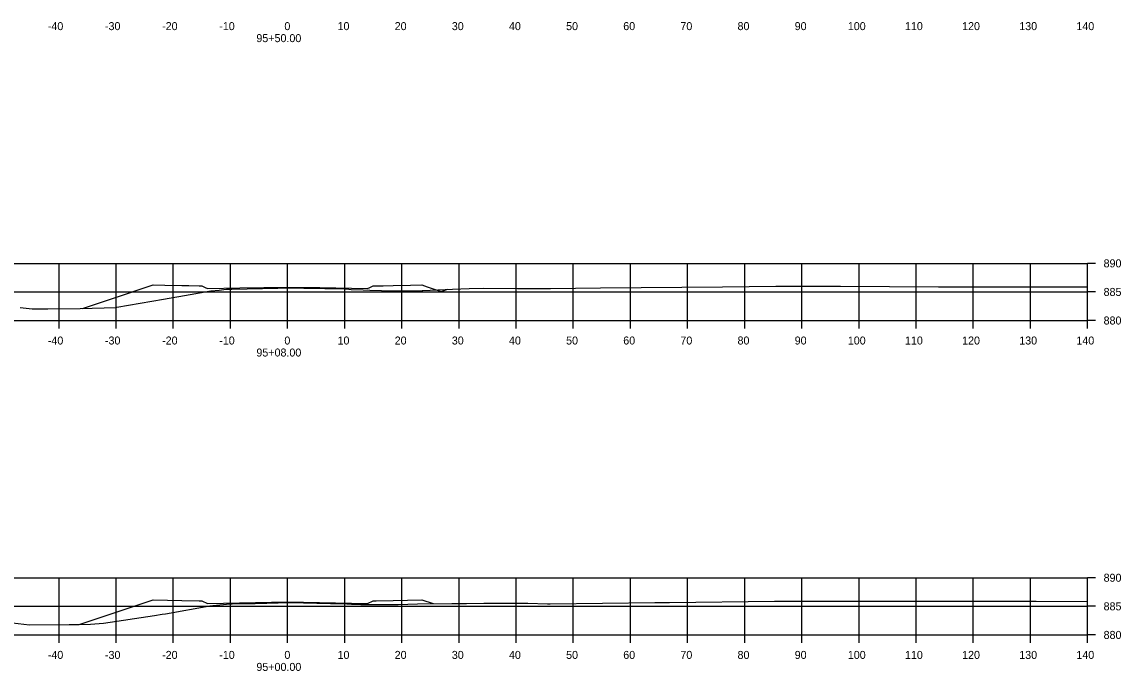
# Model space of a CAD drawing. Extents: x 1098669 to 1198896, y 698679 to 704410.
# Drawn here: x 1113452.4 to 1113644.7, y 701452.2 to 701565.8 of the extents above; entities that cross this region are included whole.
import ezdxf

# ---------------------------------------------------------------- set-up
doc = ezdxf.new("R2010")
doc.units = 0
for name, color, linetype in [('R_Alt Surface', 7, 'Continuous'), ('R_Axis', 7, 'Continuous'), ('R_Axis Annot', 7, 'Continuous'), ('R_Fin Surface', 7, 'Continuous'), ('R_Grid', 7, 'Continuous')]:
    doc.layers.add(name, color=color, linetype=linetype)

msp = doc.modelspace()

# ---------------------------------------------------------------- linework, layer by layer
at = {"layer": 'R_Alt Surface'}
for points in [[(1113452.08, 701515.81), (1113454.15, 701515.58), (1113456.94, 701515.59), (1113462.56, 701515.64), (1113468.89, 701515.86), (1113468.91, 701515.86), (1113469, 701515.87), (1113477.18, 701517.3), (1113480.82, 701517.94), (1113485.43, 701518.75), (1113486.92, 701518.89), (1113487.73, 701518.99), (1113488.18, 701519.02), (1113489.14, 701519.07), (1113497.15, 701519.23), (1113499.26, 701519.27), (1113501.73, 701519.23), (1113509.02, 701519.1), (1113509.58, 701519.05), (1113509.98, 701519.01), (1113512.08, 701518.95), (1113513.26, 701518.89), (1113517.34, 701518.77), (1113521.94, 701518.78), (1113522.43, 701518.79), (1113522.55, 701518.79), (1113527.72, 701519.07), (1113530.64, 701519.16), (1113533.08, 701519.21), (1113539.08, 701519.18), (1113540.74, 701519.17), (1113541.14, 701519.18), (1113544.85, 701519.15), (1113553.63, 701519.25), (1113574.97, 701519.44), (1113584.34, 701519.54), (1113595.62, 701519.54), (1113612.78, 701519.46), (1113618.71, 701519.47), (1113629.6, 701519.47), (1113638.87, 701519.44)], [(1113450.73, 701460.67), (1113453.7, 701460.34), (1113460.64, 701460.36), (1113462.39, 701460.38), (1113464.39, 701460.45), (1113466.65, 701460.6), (1113475.59, 701461.93), (1113476.91, 701462.16), (1113477.5, 701462.27), (1113485.26, 701463.63), (1113485.76, 701463.68), (1113487.65, 701463.89), (1113488.7, 701463.97), (1113489.18, 701464), (1113493.17, 701464.08), (1113499.28, 701464.2), (1113506.38, 701464.08), (1113509.04, 701464.03), (1113509.25, 701464.02), (1113510.03, 701463.94), (1113511.69, 701463.89), (1113514.28, 701463.9), (1113518.2, 701463.87), (1113521.61, 701464), (1113527.59, 701464.07), (1113530.19, 701464.08), (1113533.19, 701464.14), (1113536.63, 701464.13), (1113540.91, 701464.13), (1113544.37, 701464.02), (1113544.8, 701464.02), (1113563.14, 701464.22), (1113565.69, 701464.24), (1113584.08, 701464.44), (1113605.72, 701464.45), (1113607.62, 701464.44), (1113608.29, 701464.44), (1113629.88, 701464.45), (1113638.87, 701464.42)]]:
    msp.add_lwpolyline(points, dxfattribs=at)
at = {"layer": 'R_Axis'}
for p, q in [((1113638.87, 701513.56), (1113638.87, 701523.56)), ((1113640.27, 701523.56), (1113638.87, 701523.56)), ((1113640.27, 701518.56), (1113638.87, 701518.56)), ((1113358.87, 701513.56), (1113638.87, 701513.56)), ((1113458.87, 701512.16), (1113458.87, 701513.56)), ((1113468.87, 701512.16), (1113468.87, 701513.56)), ((1113478.87, 701512.16), (1113478.87, 701513.56)), ((1113488.87, 701512.16), (1113488.87, 701513.56)), ((1113498.87, 701512.16), (1113498.87, 701513.56)), ((1113508.87, 701512.16), (1113508.87, 701513.56)), ((1113518.87, 701512.16), (1113518.87, 701513.56)), ((1113528.87, 701512.16), (1113528.87, 701513.56)), ((1113538.87, 701512.16), (1113538.87, 701513.56)), ((1113548.87, 701512.16), (1113548.87, 701513.56)), ((1113558.87, 701512.16), (1113558.87, 701513.56)), ((1113568.87, 701512.16), (1113568.87, 701513.56)), ((1113578.87, 701512.16), (1113578.87, 701513.56)), ((1113588.87, 701512.16), (1113588.87, 701513.56)), ((1113598.87, 701512.16), (1113598.87, 701513.56)), ((1113608.87, 701512.16), (1113608.87, 701513.56)), ((1113618.87, 701512.16), (1113618.87, 701513.56)), ((1113628.87, 701512.16), (1113628.87, 701513.56)), ((1113638.87, 701512.16), (1113638.87, 701513.56)), ((1113640.27, 701513.56), (1113638.87, 701513.56)), ((1113638.87, 701458.56), (1113638.87, 701468.56)), ((1113640.27, 701468.56), (1113638.87, 701468.56)), ((1113640.27, 701463.56), (1113638.87, 701463.56)), ((1113358.87, 701458.56), (1113638.87, 701458.56)), ((1113458.87, 701457.16), (1113458.87, 701458.56)), ((1113468.87, 701457.16), (1113468.87, 701458.56)), ((1113478.87, 701457.16), (1113478.87, 701458.56)), ((1113488.87, 701457.16), (1113488.87, 701458.56)), ((1113498.87, 701457.16), (1113498.87, 701458.56)), ((1113508.87, 701457.16), (1113508.87, 701458.56)), ((1113518.87, 701457.16), (1113518.87, 701458.56)), ((1113528.87, 701457.16), (1113528.87, 701458.56)), ((1113538.87, 701457.16), (1113538.87, 701458.56)), ((1113548.87, 701457.16), (1113548.87, 701458.56)), ((1113558.87, 701457.16), (1113558.87, 701458.56)), ((1113568.87, 701457.16), (1113568.87, 701458.56)), ((1113578.87, 701457.16), (1113578.87, 701458.56)), ((1113588.87, 701457.16), (1113588.87, 701458.56)), ((1113598.87, 701457.16), (1113598.87, 701458.56)), ((1113608.87, 701457.16), (1113608.87, 701458.56)), ((1113618.87, 701457.16), (1113618.87, 701458.56)), ((1113628.87, 701457.16), (1113628.87, 701458.56)), ((1113638.87, 701457.16), (1113638.87, 701458.56)), ((1113640.27, 701458.56), (1113638.87, 701458.56))]:
    msp.add_line(p, q, dxfattribs=at)
at = {"layer": 'R_Fin Surface'}
for points in [[(1113462.98, 701515.65), (1113468.05, 701517.34), (1113475.37, 701519.78), (1113477.38, 701519.74), (1113480.37, 701519.68), (1113481.57, 701519.66), (1113483.37, 701519.62), (1113483.57, 701519.62), (1113483.87, 701519.62), (1113484.47, 701519.34), (1113484.87, 701519.14), (1113490.52, 701519.26), (1113498.87, 701519.42), (1113504.52, 701519.31), (1113512.87, 701519.14), (1113513.27, 701519.34), (1113513.87, 701519.62), (1113514.07, 701519.62), (1113514.37, 701519.62), (1113515.57, 701519.65), (1113517.37, 701519.68), (1113520.38, 701519.74), (1113522.37, 701519.78), (1113523.32, 701519.47), (1113525.76, 701518.65), (1113526.91, 701519.04)], [(1113462.42, 701460.38), (1113475.37, 701464.69), (1113480.37, 701464.59), (1113483.37, 701464.53), (1113483.87, 701464.53), (1113484.87, 701464.05), (1113498.87, 701464.33), (1113512.87, 701464.05), (1113513.87, 701464.53), (1113514.37, 701464.53), (1113517.37, 701464.59), (1113522.37, 701464.69), (1113524.34, 701464.03)]]:
    msp.add_lwpolyline(points, dxfattribs=at)
at = {"layer": 'R_Grid'}
for p, q in [((1113358.87, 701523.56), (1113638.87, 701523.56)), ((1113458.87, 701513.56), (1113458.87, 701523.56)), ((1113468.87, 701513.56), (1113468.87, 701523.56)), ((1113478.87, 701513.56), (1113478.87, 701523.56)), ((1113488.87, 701513.56), (1113488.87, 701523.56)), ((1113498.87, 701513.56), (1113498.87, 701523.56)), ((1113508.87, 701513.56), (1113508.87, 701523.56)), ((1113518.87, 701513.56), (1113518.87, 701523.56)), ((1113528.87, 701513.56), (1113528.87, 701523.56)), ((1113538.87, 701513.56), (1113538.87, 701523.56)), ((1113548.87, 701513.56), (1113548.87, 701523.56)), ((1113558.87, 701513.56), (1113558.87, 701523.56)), ((1113568.87, 701513.56), (1113568.87, 701523.56)), ((1113578.87, 701513.56), (1113578.87, 701523.56)), ((1113588.87, 701513.56), (1113588.87, 701523.56)), ((1113598.87, 701513.56), (1113598.87, 701523.56)), ((1113608.87, 701513.56), (1113608.87, 701523.56)), ((1113618.87, 701513.56), (1113618.87, 701523.56)), ((1113628.87, 701513.56), (1113628.87, 701523.56)), ((1113638.87, 701513.56), (1113638.87, 701523.56)), ((1113358.87, 701518.56), (1113638.87, 701518.56)), ((1113358.87, 701513.56), (1113638.87, 701513.56)), ((1113358.87, 701468.56), (1113638.87, 701468.56)), ((1113458.87, 701458.56), (1113458.87, 701468.56)), ((1113468.87, 701458.56), (1113468.87, 701468.56)), ((1113478.87, 701458.56), (1113478.87, 701468.56)), ((1113488.87, 701458.56), (1113488.87, 701468.56)), ((1113498.87, 701458.56), (1113498.87, 701468.56)), ((1113508.87, 701458.56), (1113508.87, 701468.56)), ((1113518.87, 701458.56), (1113518.87, 701468.56)), ((1113528.87, 701458.56), (1113528.87, 701468.56)), ((1113538.87, 701458.56), (1113538.87, 701468.56)), ((1113548.87, 701458.56), (1113548.87, 701468.56)), ((1113558.87, 701458.56), (1113558.87, 701468.56)), ((1113568.87, 701458.56), (1113568.87, 701468.56)), ((1113578.87, 701458.56), (1113578.87, 701468.56)), ((1113588.87, 701458.56), (1113588.87, 701468.56)), ((1113598.87, 701458.56), (1113598.87, 701468.56)), ((1113608.87, 701458.56), (1113608.87, 701468.56)), ((1113618.87, 701458.56), (1113618.87, 701468.56)), ((1113628.87, 701458.56), (1113628.87, 701468.56)), ((1113638.87, 701458.56), (1113638.87, 701468.56)), ((1113358.87, 701463.56), (1113638.87, 701463.56)), ((1113358.87, 701458.56), (1113638.87, 701458.56))]:
    msp.add_line(p, q, dxfattribs=at)

# ---------------------------------------------------------------- texts
at = {"layer": 'R_Axis Annot'}
for s, p in [('-40', (1113456.91, 701564.36)), ('-30', (1113466.91, 701564.36)), ('-20', (1113476.91, 701564.36)), ('-10', (1113486.91, 701564.36)), ('0', (1113498.31, 701564.36)), ('10', (1113507.61, 701564.36)), ('20', (1113517.61, 701564.36)), ('30', (1113527.61, 701564.36)), ('40', (1113537.61, 701564.36)), ('50', (1113547.61, 701564.36)), ('60', (1113557.61, 701564.36)), ('70', (1113567.61, 701564.36)), ('80', (1113577.61, 701564.36)), ('90', (1113587.61, 701564.36)), ('100', (1113596.91, 701564.36)), ('110', (1113606.91, 701564.36)), ('120', (1113616.91, 701564.36)), ('130', (1113626.91, 701564.36)), ('140', (1113636.91, 701564.36)), ('95+50.00', (1113493.41, 701562.26)), ('890', (1113641.67, 701522.86)), ('885', (1113641.67, 701517.86)), ('880', (1113641.67, 701512.86)), ('-40', (1113456.91, 701509.36)), ('-30', (1113466.91, 701509.36)), ('-20', (1113476.91, 701509.36)), ('-10', (1113486.91, 701509.36)), ('0', (1113498.31, 701509.36)), ('10', (1113507.61, 701509.36)), ('20', (1113517.61, 701509.36)), ('30', (1113527.61, 701509.36)), ('40', (1113537.61, 701509.36)), ('50', (1113547.61, 701509.36)), ('60', (1113557.61, 701509.36)), ('70', (1113567.61, 701509.36)), ('80', (1113577.61, 701509.36)), ('90', (1113587.61, 701509.36)), ('100', (1113596.91, 701509.36)), ('110', (1113606.91, 701509.36)), ('120', (1113616.91, 701509.36)), ('130', (1113626.91, 701509.36)), ('140', (1113636.91, 701509.36)), ('95+08.00', (1113493.41, 701507.26)), ('890', (1113641.67, 701467.86)), ('885', (1113641.67, 701462.86)), ('880', (1113641.67, 701457.86)), ('-40', (1113456.91, 701454.36)), ('-30', (1113466.91, 701454.36)), ('-20', (1113476.91, 701454.36)), ('-10', (1113486.91, 701454.36)), ('0', (1113498.31, 701454.36)), ('10', (1113507.61, 701454.36)), ('20', (1113517.61, 701454.36)), ('30', (1113527.61, 701454.36)), ('40', (1113537.61, 701454.36)), ('50', (1113547.61, 701454.36)), ('60', (1113557.61, 701454.36)), ('70', (1113567.61, 701454.36)), ('80', (1113577.61, 701454.36)), ('90', (1113587.61, 701454.36)), ('100', (1113596.91, 701454.36)), ('110', (1113606.91, 701454.36)), ('120', (1113616.91, 701454.36)), ('130', (1113626.91, 701454.36)), ('140', (1113636.91, 701454.36)), ('95+00.00', (1113493.41, 701452.26))]:
    msp.add_text(s, height=1.4, dxfattribs=at).set_placement(p)

doc.saveas('drawing.dxf')
